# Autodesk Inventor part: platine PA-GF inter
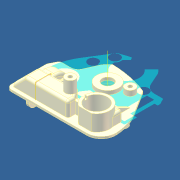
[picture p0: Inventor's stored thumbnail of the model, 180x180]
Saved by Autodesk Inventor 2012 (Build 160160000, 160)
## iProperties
Created: 2011-07
Part Number: platine PA-GF inter
Document SubType Name: Modeling
Designer: Laur
Density: 1.13 g/cm^3
Material: Nylon - 6/6
Mass: 2.66326 g
Surface Area: 28.7081 cm^2
Volume: 2.35687 cm^3
Author: Laur
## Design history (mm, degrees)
sketch "Esquisse1"
  geometry: L1 (-32.1, 11.5)-(26.596, 11.5); L2 (26.596, 11.5)-(26.596, -43.876); L3 (26.596, -43.876)-(-32.1, -43.876); L4 (-32.1, -43.876)-(-32.1, 11.5); L5 (-26.823, -26.616)-(23.17, -27.471); L6 (-20.7, -5)-(-20.7, -19.1); L7 (12.39, -21.5)-(-18.3, -21.5); L8 (9.43, 5.794)-(15.506, -3.93); L9 (-20.482, -4.092)-(-19.208, -1.592); L10 (-13.9, -0.5)-(-17.426, -0.5); L11 (-9.341, 6.094)-(-11.616, 0.983); L12 (-6.696, 9.093)-(-8.758, 6.958); L13 (-20.1, -19.1)-(-20.1, -5); L14 (-19.947, -4.364)-(-18.674, -1.864); L15 (-17.426, -1.1)-(-13.9, -1.1); L16 (-11.068, 0.739)-(-8.793, 5.85); L17 (-8.326, 6.541)-(-6.447, 8.488); L18 (9.025, 5.31)-(14.997, -4.248); L19 (12.39, -20.9)-(-18.3, -20.9); C1 r 1.77 at (0, 0); C2 r 0.8 at (6.9, 2.25); C3 r 4.3 at (10.3, -14.8); C4 r 1.053 at (-10.659, -17.286); C5 r 2 at (0, -15.2); C6 r 2 at (6.9, 2.25); C7 r 0.8 at (0, -15.2); C8 r 1.77 at (-1.149, -7.006); A1 r 2.4 centre (-18.3, -19.1) between (-20.7, -19.1) and (-18.3, -21.5); A2 r 6.5 centre (12.39, -15) between (12.39, -21.5) and (18.882, -14.673); A3 r 22.4 centre (-3.49, -15.8) between (18.882, -14.673) and (15.506, -3.93); A4 r 2 centre (-18.7, -5) between (-20.482, -4.092) and (-20.7, -5); A5 r 2 centre (-17.426, -2.5) between (-17.426, -0.5) and (-19.208, -1.592); A6 r 2.5 centre (-13.9, 2) between (-13.9, -0.5) and (-11.616, 0.983); A7 r 3 centre (-6.6, 4.874) between (-8.758, 6.958) and (-9.341, 6.094); A8 r 45 centre (-7.5, -35.9) between (9.43, 5.794) and (-6.696, 9.093); A9 r 1.4 centre (-18.7, -5) between (-19.947, -4.364) and (-20.1, -5); A10 r 1.4 centre (-17.426, -2.5) between (-17.426, -1.1) and (-18.674, -1.864); A11 r 3.1 centre (-13.9, 2) between (-13.9, -1.1) and (-11.068, 0.739); A12 r 2.4 centre (-6.6, 4.874) between (-8.326, 6.541) and (-8.793, 5.85); A13 r 44.4 centre (-7.5, -35.9) between (9.025, 5.31) and (-6.447, 8.488); A14 r 21.8 centre (-3.49, -15.8) between (18.282, -14.703) and (14.997, -4.248); A15 r 5.9 centre (12.39, -15) between (12.39, -20.9) and (18.282, -14.703); A16 r 1.8 centre (-18.3, -19.1) between (-20.1, -19.1) and (-18.3, -20.9); 1 further point; 1 other entity
  constraints: 32 point on circle, 30 end point, 24 centre point, 13 tangent, 3 coincident, 2 parallel, 2 perpendicular, 1 horizontal, 1 vertical, 16 other
  dimensions: "d44" = 50 distance of L5.start L5.end; "d141" = 3.54 diameter of C1; "d142" = 4 diameter of C6; "d143" = 1.6 diameter of C2; "d144" = 4 diameter of C5 (= d142); "d145" = 1.6 diameter of C7 (= d143); "d150" = 2.4 radius of A1; "d176" = 2.25 vertical distance of C6.centre point (0, 0); "d181" = 21.5 distance from line of L7 point (0, 0); "d184" = 20.7 distance from line of point (0, 0) L6; "d205" = 13 diameter of A2; "d206" = 58 deg angle of L7 L8; "d210" = 6.9 horizontal distance of C2.centre point (0, 0); "d211" = 0 horizontal distance of C7.centre point (0, 0); "d212" = 15.2 distance of C7.centre point (0, 0); "d243" = 15.8 vertical distance of A3.centre point (0, 0); "d244" = 3.49 horizontal distance of point (0, 0) A3.centre; "d245" = 10.3 horizontal distance of C3.centre point (0, 0); "d246" = 14.8 vertical distance of point (0, 0) C3.centre; "d254" = 22.4 radius of A3; "d261" = 8.6 diameter of C3; "d268" = 27 deg angle of L6 L9; "d279" = 16.5 distance from line of L6.start L7; "d280" = 4 diameter of A4; "d281" = 21 distance between parallel lines of L10 L7; "d284" = 4 diameter of A5; "d302" = 114 deg angle of L10 L11; "d308" = 5 diameter of A6; "d309" = 6.8 distance from line of A6.centre L6; "d317" = 6 diameter of A7; "d320" = 6.6 horizontal distance of A7.centre point (0, 0); "d322" = 160 deg angle of L12 L11; "d326" = 90 diameter of A8; "d327" = 7.5 horizontal distance of A8.centre C1.centre; "d328" = 35.9 vertical distance of A8.centre C1.centre; "d335" = 0.6 distance between parallel lines of L6 L13; "d349" = 38.38239 distance from line of A14.start L13 (derived); "d388" = 3.54 diameter of C8; "d499" = 11.5 distance from line of L1 point (0, 0); "d500" = 32.1 distance from line of point (0, 0) L4; "d502" = 7.1 distance of C8.centre point (0, 0)
extrude "contour ext - ép 0,8" new body sketch "Esquisse1" distance "d336" = 0.8; taper "d337" = 0 deg
sketch "Esquisse2"
  geometry: L1 (20.1, -19.1)-(20.1, -5) reference; L2 (19.947, -4.364)-(18.674, -1.864) reference; L3 (17.426, -1.1)-(13.9, -1.1) reference; L4 (11.068, 0.739)-(8.793, 5.85) reference; L5 (8.326, 6.541)-(6.447, 8.488) reference; L6 (-9.025, 5.31)-(-14.997, -4.248) reference; L7 (-12.39, -20.9)-(18.3, -20.9) reference; L8 (-13.81, -4.99)-(-8.082, 4.177); L9 (5.87, 7.069)-(7.319, 5.568); L10 (7.514, 5.281)-(9.789, 0.17); L11 (13.9, -2.5)-(17.426, -2.5); L12 (17.426, -2.5)-(18.7, -5); L13 (18.7, -5)-(18.7, -19.1); L14 (18.3, -19.5)-(-12.39, -19.5); C1 r 4.3 at (-10.3, -14.8) reference; C2 r 2 at (-6.9, 2.25) reference; C3 r 2 at (0, -15.2) reference; C4 r 1.77 at (0, 0) reference; C5 r 1.053 at (10.659, -17.286) reference; A1 r 1.4 centre (18.7, -5) between (20.1, -5) and (19.947, -4.364) reference; A2 r 1.4 centre (17.426, -2.5) between (18.674, -1.864) and (17.426, -1.1) reference; A3 r 3.1 centre (13.9, 2) between (11.068, 0.739) and (13.9, -1.1) reference; A4 r 2.4 centre (6.6, 4.874) between (8.793, 5.85) and (8.326, 6.541) reference; A5 r 44.4 centre (7.5, -35.9) between (6.447, 8.488) and (-9.025, 5.31) reference; A6 r 21.8 centre (3.49, -15.8) between (-14.997, -4.248) and (-18.282, -14.703) reference; A7 r 5.9 centre (-12.39, -15) between (-18.282, -14.703) and (-12.39, -20.9) reference; A8 r 1.8 centre (18.3, -19.1) between (18.3, -20.9) and (20.1, -19.1) reference; A9 r 43 centre (7.5, -35.9) between (5.87, 7.069) and (-8.082, 4.177); A10 r 1 centre (6.6, 4.874) between (7.514, 5.281) and (7.319, 5.568); A11 r 4.5 centre (13.9, 2) between (9.789, 0.17) and (13.9, -2.5); A12 r 0 centre (17.426, -2.5) between (17.426, -2.5) and (17.426, -2.5); A13 r 0 centre (18.7, -5) between (18.7, -5) and (18.7, -5); A14 r 0.4 centre (18.3, -19.1) between (18.3, -19.5) and (18.7, -19.1); A15 r 4.5 centre (-12.39, -15) between (-16.884, -14.774) and (-12.39, -19.5); A16 r 20.4 centre (3.49, -15.8) between (-13.81, -4.99) and (-16.884, -14.774); 2 further points
  constraints: 14 end point, 12 point on circle, 8 centre point, 4 coincident with centre, 14 other
  dimensions: "d518" = 1.4 distance between parallel lines of L1 L13
extrude "centrage int - ép 0,8" join sketch "Esquisse2" distance "d339" = 0.8; taper "d340" = 0 deg
sketch "Esquisse3"
  geometry: C1 r 2 at (6.9, 2.25) reference; C2 r 0.8 at (6.9, 2.25)
  constraints: 1 centre point, 1 coincident
  dimensions: "d341" = 1.6 diameter of C2
extrude "bossage1 fix capot" join sketch "Esquisse3" stored distance "d342" = 5.8; taper "d343" = 0 deg
sketch "Esquisse4"
  geometry: C1 r 2 at (0, 0) reference; C2 r 0.8 at (0, 0)
  constraints: 1 centre point, 1 coincident
  dimensions: "d344" = 1.6 diameter of C2
extrude "alésage1 pour vis fix capot" cut sketch "Esquisse4" distance "d345" = 5; taper "d346" = 0 deg
sketch "Esquisse5"
  geometry: L1 (13.81, -4.99)-(8.082, 4.177) reference; L2 (-5.87, 7.069)-(-7.319, 5.568) reference; L3 (-7.514, 5.281)-(-9.789, 0.17) reference; L4 (-13.9, -2.5)-(-17.426, -2.5) reference; L5 (-17.426, -2.5)-(-18.7, -5) reference; L6 (-18.7, -5)-(-18.7, -19.1) reference; L7 (-18.3, -19.5)-(12.39, -19.5) reference; L8 (3.4, -19.5)-(-18.7, -19.5); L9 (-18.7, -19.5)-(-18.7, -13.2); L10 (-18.7, -13.2)-(1.041, -13.2); L11 (3.4, -16.569)-(3.4, -19.5); L12 (1.041, -13.2)-(3.4, -16.569); C1 r 2 at (0, -15.2) reference; A1 r 43 centre (-7.5, -35.9) between (8.082, 4.177) and (-5.87, 7.069) reference; A2 r 1 centre (-6.6, 4.874) between (-7.319, 5.568) and (-7.514, 5.281) reference; A3 r 4.5 centre (-13.9, 2) between (-13.9, -2.5) and (-9.789, 0.17) reference; A4 r 0.4 centre (-18.3, -19.1) between (-18.7, -19.1) and (-18.3, -19.5) reference; A5 r 4.5 centre (12.39, -15) between (12.39, -19.5) and (16.884, -14.774) reference; A6 r 20.4 centre (-3.49, -15.8) between (16.884, -14.774) and (13.81, -4.99) reference
  constraints: 10 end point, 2 parallel, 2 point on line, 2 tangent, 1 horizontal, 1 perpendicular
  dimensions: "d521" = 55 deg angle of L10 L12; "d522" = 22.1 distance between parallel lines of L11 L6
extrude "bossage loge carte" join sketch "Esquisse5" distance "d523" = 6; taper "d524" = 0 deg
sketch "Esquisse6"
  geometry: C1 r 2 at (0, -15.2); A1 r 2 centre (0, -15.2) between (0, -13.2) and (1.638, -14.053) reference
  constraints: 1 centre point, 1 coincident, 1 concentric
extrude "bossage2 fix capot" join sketch "Esquisse6" distance "d525" = 4.8; taper "d526" = 0 deg
sketch "Esquisse7"
  geometry: C1 r 2 at (0, -15.2) reference; C2 r 0.8 at (0, -15.2)
  constraints: 1 centre point, 1 coincident
  dimensions: "d530" = 1.6 diameter of C2
extrude "alésage2 pour vis fix capot" cut sketch "Esquisse7" distance "d528" = 5; taper "d529" = 0 deg
sketch "Esquisse8"
  geometry: L1 (1.041, -13.2)-(1.638, -14.053); L2 (1.638, -14.053)-(3.4, -16.569); L3 (-17.426, -1.1)-(-13.9, -1.1); L4 (15.45, -13.351)-(15.45, -9.25); L5 (15.45, -9.25)-(9.549, -9.25); L6 (9.549, -9.25)-(1.041, -13.2); L7 (7.744, -19.5)-(12.856, -19.5); L8 (3.4, -19.5)-(-18.3, -19.5); L9 (3.4, -16.569)-(5.251, -16.569); L10 (3.4, -19.5)-(-18.7, -19.5) reference; C1 r 4.3 at (10.3, -14.8); C2 r 4.3 at (10.3, -14.8) reference; A1 r 5.35 centre (10.3, -14.8) between (12.856, -19.5) and (7.744, -19.5)
  constraints: 18 end point, 4 point on circle, 2 centre point, 2 coincident, 2 collinear, 2 parallel, 2 perpendicular, 1 tangent
  dimensions: "d531" = 10.7 diameter of A1; "d533" = 5.55 distance from line of L5 C1.centre; "d534" = 5.15 distance from line of L4 C1.centre
extrude "bossage connect ph1" join sketch "Esquisse8" distance "d535" = 2.3; taper "d536" = 0 deg
sketch "Esquisse9"
  geometry: L1 (15.45, -9.25)-(15.45, -13.351) reference; L2 (9.549, -9.25)-(15.45, -9.25) reference; L3 (1.041, -13.2)-(9.549, -9.25) reference; L4 (5.251, -16.569)-(3.4, -16.569) reference; L5 (12.856, -19.5)-(7.744, -19.5) reference; C1 r 4.3 at (10.3, -14.8) reference; A1 r 5.35 centre (10.3, -14.8) between (12.856, -19.5) and (15.45, -13.351) reference; A2 r 5.35 centre (10.3, -14.8) between (5.251, -16.569) and (7.744, -19.5) reference; A3 r 5.35 centre (10.3, -14.8) between (8.047, -9.947) and (5.251, -16.569)
  constraints: 3 point on circle, 2 point on line, 1 centre point, 1 coincident, 1 end point
extrude "bossage connect ph2" join sketch "Esquisse9" distance "d537" = 1.8; taper "d538" = 0 deg
sketch "Esquisse10"
  geometry: L1 (12.856, -19.5)-(7.744, -19.5) reference; L2 (15.45, -9.25)-(15.45, -13.351) reference; L3 (9.549, -9.25)-(15.45, -9.25) reference; L4 (8.047, -9.947)-(9.549, -9.25) reference; C1 r 4.3 at (10.3, -14.8) reference; A1 r 5.35 centre (10.3, -14.8) between (12.856, -19.5) and (15.45, -13.351) reference; A2 r 5.35 centre (10.3, -14.8) between (8.047, -9.947) and (7.744, -19.5) reference; A3 r 5.35 centre (10.3, -14.8) between (15.45, -13.351) and (8.047, -9.947)
  constraints: 2 end point, 2 point on circle, 1 centre point, 1 coincident, 1 concentric, 1 point on line
extrude "bossage connect ph3" join sketch "Esquisse10" distance "d539" = 2.4; taper "d540" = 0 deg
sketch "Esquisse12"
  geometry: L1 (3.4, -16.569)-(1.041, -13.2) reference; L2 (5.251, -16.569)-(3.4, -16.569) reference; L3 (2.7, -15.569)-(5.006, -15.569); A1 r 5.35 centre (10.3, -14.8) between (8.047, -9.947) and (5.251, -16.569) reference
  constraints: 2 end point, 1 parallel, 1 point on circle, 1 point on line
  dimensions: "d541" = 1 distance between parallel lines of L2 L3
extrude "nervure connect à  loge carte" join sketch "Esquisse12" distance "d542" = 2.4; taper "d543" = 0 deg
node "Plan de construction1"
sketch "Esquisse14"
  geometry: L1 (1.6, 2.851)-(1.6, -5.749) reference; L2 (0, 0)-(-4.1, 0) reference; L3 (0, 4.101)-(0, 0) reference; L4 (0, 4.101)-(-4.1, 4.101) reference; L5 (-4.1, 4.101)-(-4.1, 0) reference; L6 (-3, 4.101)-(0, 10.101); L7 (0, -1.352)-(0, 9.103) reference; L8 (0, 18.661)-(0, 9.103) reference
  constraints: 2 end point, 2 point on line
  dimensions: "d548" = 6 distance from line of L6.end L4; "d549" = 3 distance from line of L6.start L7
feature "Nervure connect à platine" sketch "Esquisse14" dims "d550" = 1, "d551" = 1, "d552" = 0
node "Plan de construction bossage lat"
sketch "Esquisse16"
  geometry: L1 (0, 0.4)-(0, 14.5); L2 (2.5, 5.9)-(2.5, 10.4); L3 (0, 15.136)-(0, 14.5); L4 (0, 15.136)-(0, 17.636); L5 (0, 6)-(0, 15.273); A1 r 6 centre (-3.5, 10.4) between (2.5, 10.4) and (0, 15.273); 2 further points; 1 other entity
  constraints: 10 end point, 2 point on circle, 1 centre point, 1 parallel, 1 point on line, 1 tangent, 4 other
  dimensions: "d554" = 12 diameter of A1; "d555" = 4.5 dimension on A1.centre; "d556" = 2.5 distance between parallel lines of L2 L1
extrude "bossage latéral loge carte" join sketch "Esquisse16" stored distance "d557" = 5.3; taper "d558" = 0 deg
sketch "Esquisse20"
  geometry: L1 (2.5, 6.3)-(2.5, 10.4) reference; L2 (1.3, 3.323)-(1.3, 10.2); L3 (-1.6, 14.5)-(-1.6, 0.4) reference; L4 (1.3, 3.323)-(-1.6, 3.323); L5 (-1.6, 14.5)-(-1.6, 14.812); A1 r 6 centre (-3.5, 10.4) between (2.5, 10.4) and (0, 15.273) reference; A2 r 4.804 centre (-3.5, 10.4) between (1.3, 10.2) and (-1.6, 14.812)
  constraints: 6 end point, 2 perpendicular, 2 point on circle, 1 centre point, 1 point on line
  dimensions: "d564" = 1.2 distance between parallel lines of L2 L1
extrude "évidemment bossage lat" cut sketch "Esquisse20" stored distance "d565" = 2.9; taper "d566" = 0 deg
sketch "Esquisse22"
  geometry: 2 further points
  constraints: 1 other
extrude "Extrusion17" join sketch "Esquisse22" stored distance "d574" = 6; taper "d575" = 0 deg
sketch "Esquisse21"
  geometry: L1 (18.7, -13.2)-(0, -13.2) reference; L2 (-3.4, -16.569)-(-3.4, -19.5) reference; L3 (-1.638, -14.053)-(-3.4, -16.569) reference; L4 (-1.041, -13.2)-(-1.638, -14.053) reference; L5 (0, -13.2)-(-1.041, -13.2) reference; L6 (18.3, -19.5)-(-12.39, -19.5) reference; L7 (-2.2, -18.3)-(17.5, -18.3); L8 (17.5, -18.3)-(17.5, -14.4); L9 (17.5, -14.4)-(-0.416, -14.4); L10 (-0.416, -14.4)-(-2.2, -16.947); L11 (-2.2, -16.947)-(-2.2, -18.3); L12 (18.7, -19.5)-(18.7, -13.2) reference; L13 (-3.4, -19.5)-(18.7, -19.5) reference; C1 r 2 at (0, -15.2) reference; A1 r 2 centre (0, -15.2) between (-1.638, -14.053) and (0, -13.2) reference; A2 r 2 centre (0, -15.2) between (0, -13.2) and (-1.638, -14.053) reference
  constraints: 10 end point, 4 parallel, 1 perpendicular
  dimensions: "d569" = 1.2 distance between parallel lines of L7 L6; "d570" = 1.2 distance between parallel lines of L2 L11 (derived); "d571" = 1.2 distance between parallel lines of L3 L10 (derived); "d572" = 1.2 distance between parallel lines of L1 L9 (derived)
extrude "forme1 logement pcb" cut sketch "Esquisse21" distance "d567" = 6.4; taper "d568" = 0 deg
sketch "Esquisse23"
  geometry: L1 (0, 6)-(0, 0) reference; L2 (0, 0)-(18.7, 0) reference; L3 (4.5, 0)-(0, 4.5)
  constraints: 2 end point, 2 point on line
  dimensions: "d576" = 4.5 distance from line of L1 L3.start; "d577" = 4.5 distance from line of L3.end L2
extrude "forme2 logement pcb" cut sketch "Esquisse23" stored distance "d578" = 6; taper "d579" = 0 deg
sketch "Esquisse24"
  geometry: L1 (-2.35, 6.4)-(-4.45, 4.3) reference; L2 (-4.45, 0)-(-4.45, 4.3) reference; L3 (-2.35, 6.4)-(13.466, 6.4) reference; L4 (-0.653, 6.4)-(-4.45, 2.603)
  constraints: 2 end point, 2 point on line, 1 parallel
  dimensions: "d580" = 1.2 distance between parallel lines of L1 L4
extrude "forme3 logement pcb" join sketch "Esquisse24" stored distance "d581" = 6; taper "d582" = 0 deg
fillet "arrondis platine" dims "d583" = 1
node "Axe de construction1"
sketch "Esquisse25"
  geometry: L1 (6.029, -15.3)-(4.95, -15.3); L2 (4.95, -15.3)-(4.95, -14.3); L3 (4.95, -14.3)-(6.029, -14.3); L4 (6.029, -14.3)-(6.029, -15.3); A1 r 4.3 centre (10.3, -14.8) between (6.029, -14.3) and (6.029, -15.3) reference; A2 r 5.35 centre (10.3, -14.8) between (12.856, -19.5) and (7.744, -19.5) reference
  constraints: 8 end point, 2 parallel, 2 point on circle, 1 horizontal, 1 perpendicular, 1 tangent
  dimensions: "d586" = 1 distance between parallel lines of L1 L3
extrude "évidemment pour ergot connecteur" cut sketch "Esquisse25" distance "d587" = 1; taper "d588" = 0 deg
sketch "Esquisse26"
  geometry: L1 (-0.416, -14.4)-(17.5, -14.4) reference; L2 (18.7, -5)-(18.7, -19.1) reference; L3 (18.7, -14.4)-(17.4, -14.4); L4 (17.4, -14.4)-(17.4, -6); L5 (17.4, -6)-(18.7, -6); L6 (18.7, -6)-(18.7, -14.4); 1 further point
  constraints: 8 end point, 2 parallel, 1 collinear, 1 horizontal, 1 perpendicular, 1 point on line
  dimensions: "d589" = 8.4 distance between parallel lines of L3 L5; "d590" = 1.3 distance between parallel lines of L6 L4
extrude "forme logement butée axiale" join sketch "Esquisse26" distance "d591" = 8.5; taper "d592" = 0 deg
fillet "arrondi forme logement butée axiale" dims "d593" = 2
sketch "Esquisse27"
  geometry: L1 (-0.8, 4.7)-(-7.3, 4.7) reference; L2 (-0.8, 4.7)-(-0.8, 0) reference; L3 (-7.9, 6.35)-(-2.8, 6.35); L4 (-2.8, 6.35)-(-2.8, 11.45); L5 (-2.8, 11.45)-(-7.9, 11.45); L6 (-7.9, 11.45)-(-7.9, 6.35); 1 further point
  constraints: 8 end point, 2 parallel, 1 horizontal, 1 perpendicular
  dimensions: "d594" = 5.1 distance between parallel lines of L5 L3; "d595" = 5.1 distance between parallel lines of L4 L6; "d596" = 1.65 distance between parallel lines of L1 L3; "d597" = 2 distance between parallel lines of L2 L4
extrude "logement butée axiale" cut sketch "Esquisse27" distance "d598" = 1; taper "d599" = 0 deg
sketch "Esquisse28"
  geometry: L1 (18.7, -12.4)-(17.4, -12.4) reference; L2 (17.4, -12.4)-(17.4, -8) reference; L3 (17.4, -11.85)-(17.9, -11.85); L4 (17.9, -11.85)-(17.9, -8.55); L5 (17.9, -8.55)-(17.4, -8.55); L6 (17.4, -8.55)-(17.4, -11.85)
  constraints: 8 end point, 2 parallel, 1 horizontal, 1 perpendicular, 1 point on line
  dimensions: "d600" = 3.3 distance between parallel lines of L5 L3; "d601" = 0.55 distance between parallel lines of L1 L3; "d602" = 0.5 distance between parallel lines of L2 L4
extrude "evidemment1 pour extrémité arbre vis" cut sketch "Esquisse28" distance "d603" = 4.5; taper "d604" = 0 deg
sketch "Esquisse29"
  geometry: L1 (-4.8, 10.55)-(-4.8, 7.25) reference; L2 (-4.8, 7.25)-(-7.9, 7.25) reference; A1 r 1.65 centre (-4.8, 8.9) between (-4.8, 7.25) and (-4.8, 10.55)
  constraints: 2 end point, 2 point on circle, 1 centre point, 1 midpoint
extrude "evidemment2 pour extrémité arbre vis" cut sketch "Esquisse29" stored distance "d605" = 4.5; taper "d606" = 0 deg
sketch "Esquisse30"
  geometry: L1 (15.95, -14.4)-(17.4, -14.4) reference; L2 (10.69, -3.7)-(-9.81, -3.7); C1 r 1.7 at (10.69, -3.7) reference; C2 r 1.7 at (10.69, -3.7) reference; C3 r 1 at (-9.81, -3.7) reference; C4 r 1 at (10.69, -3.7) reference; C5 r 0.665 at (10.69, -3.7); C6 r 0.665 at (-9.81, -3.7); C7 r 1.77 at (0, 0) reference; A1 r 2 centre (10.69, -3.7) between (11.19, -5.636) and (8.798, -3.051) reference; A2 r 1.7 centre (-9.81, -3.7) between (-8.443, -2.689) and (-8.112, -3.616) reference; A3 r 1.7 centre (-9.81, -3.7) between (-8.443, -2.689) and (-8.112, -3.616) reference; A4 r 1.7 centre (-9.81, -3.7) between (-8.443, -2.689) and (-8.112, -3.616) reference; A5 r 1.7 centre (-9.81, -3.7) between (-8.443, -2.689) and (-8.112, -3.616) reference; A6 r 2 centre (-9.81, -3.7) between (-8.47, -2.216) and (-11.461, -2.571) reference; 1 further point
  constraints: 5 coincident, 2 centre point, 2 end point, 1 parallel, 9 other
  dimensions: "d616" = 1.33 diameter of C5; "d617" = 1.33 diameter of C6 (derived); "d672" = 3.7 distance from line of L2 C7.centre (derived)
  node "Référence1"
  node "Référence2"
  node "Référence3"
  node "Référence4"
  node "Référence5"
  node "Référence6"
  node "Référence7"
  node "Référence8"
  node "Référence9"
  node "Référence10"
node "Plan de construction4"
extrude "piliers cage" join sketch "Esquisse30" stored distance "d618" = 4.5; taper "d619" = 0 deg
sketch "Esquisse31"
  geometry: C1 r 2 at (0, 0) reference; C2 r 2 at (-20.5, 0) reference; C3 r 1.7 at (0, 0) reference; A1 r 1.7 centre (-20.5, 0) between (-19.133, 1.011) and (-18.802, 0.084) reference; 1 further point
  constraints: 1 coincident, 3 other
extrude "centrages cage" join sketch "Esquisse31" distance "d620" = 1; taper "d621" = 0 deg
sketch "Esquisse32"
  geometry: C1 r 1.77 at (0, 0) reference; C2 r 2 at (-6.9, 2.25) reference; C3 r 3.75 at (0, 0); A1 r 5.25 centre (0, 0) between (-5.236, 0.384) and (-4.456, 2.776); A2 r 2.5 centre (-6.9, 2.25) between (-4.456, 2.776) and (-5.236, 0.384)
  constraints: 4 point on circle, 3 centre point, 3 coincident
  dimensions: "d624" = 10.5 diameter of A1; "d625" = 7.5 diameter of C3; "d626" = 5 diameter of A2
extrude "bossage pour palier" join sketch "Esquisse32" distance "d627" = 2.5; taper "d628" = 0 deg
sketch "Esquisse33"
  geometry: C1 r 1.77 at (0, 0) reference; C2 r 4.5 at (0, 0); C3 r 2.25 at (0, 0)
  constraints: 2 centre point, 2 coincident
  dimensions: "d629" = 9 diameter of C2; "d630" = 4.5 diameter of C3
extrude "bossage pour joint" join sketch "Esquisse33" distance "d631" = 1.5; taper "d632" = 0 deg
sketch "Esquisse34"
  geometry: C1 r 2.25 at (0, 0) reference
extrude "passage arbre de sortie" cut sketch "Esquisse34" stored distance "d633" = 5; taper "d634" = 0 deg
sketch "Esquisse35"
  geometry: C1 r 2.25 at (0, 0) reference; C2 r 3.75 at (0, 0) reference; C3 r 3.4 at (0, 0)
  constraints: 1 centre point, 1 coincident
  dimensions: "d635" = 6.8 diameter of C3
extrude "logement joint torique" cut sketch "Esquisse35" distance "d636" = 2; taper "d637" = 0 deg
node "Plan de construction nervure 2"
sketch "Esquisse36"
  geometry: L1 (4.8, 1.2)-(4.8, 5.1) reference; L2 (4.8, 5.1)-(-1.6, 5.1) reference; L3 (-1.6, 5.1)-(-1.6, 14.062) reference; L4 (-1.6, 14.062)-(-7.05, 14.062) reference; L5 (-7.05, 14.062)-(-7.05, 14.418) reference; L6 (-7.05, 14.418)-(-6.05, 14.418) reference; L7 (-6.05, 14.418)-(-6.05, 17.182) reference; L8 (-6.05, 17.182)-(-7.05, 17.182) reference; L9 (-7.05, 17.182)-(-7.05, 17.538) reference; L10 (-7.05, 17.538)-(-1.6, 17.538) reference; L11 (-1.6, 17.538)-(-1.6, 19.87) reference; L12 (-1.6, 19.87)-(-0.8, 19.87) reference; L13 (-0.8, 19.87)-(-0.8, 23.312) reference; L14 (-0.8, 23.312)-(0, 23.312) reference; L15 (0, 23.312)-(0, 6.3) reference; L16 (0, 6.3)-(5, 6.3) reference; L17 (6, 5.3)-(6, 1) reference; L18 (5, 0)-(0, 0) reference; L19 (0, 0)-(0, -1.4) reference; L20 (0, -1.4)-(-0.8, -1.4) reference; L21 (-0.8, -1.4)-(-0.8, 0) reference; L22 (-0.8, 0)-(-1.6, 0) reference; L23 (-1.6, 0)-(-1.6, 1.2) reference; L24 (-1.6, 1.2)-(4.8, 1.2) reference; L25 (4, 6.3)-(0, 13.3); L26 (0, 13.3)-(0, 6.3); L27 (0, 6.3)-(4, 6.3); L28 (4, 6.3)-(0, 13.3); L29 (0, 13.3)-(0, 6.3); L30 (4, 6.3)-(0, 6.3); A1 r 1 centre (5, 5.3) between (6, 5.3) and (5, 6.3) reference; A2 r 1 centre (5, 1) between (5, 0) and (6, 1) reference
  constraints: 12 end point, 5 collinear, 2 point on line
  dimensions: "d638" = 7 distance from line of L25.end L16; "d639" = 4 distance from line of L15 L25.start
feature "Nervure2 logement pcb" sketch "Esquisse36" dims "d640" = 1, "d641" = 1.1, "d642" = 0
node "Plan de construction nervure 3"
sketch "Esquisse37"
  geometry: L1 (-1.3, -1.931)-(-1.3, 2.369) reference; L2 (-0.3, 3.369)-(4.7, 3.369) reference; L3 (4.7, 18.424)-(4.7, 24.938) reference; L4 (4.7, 24.938)-(5.5, 24.938) reference; L5 (5.5, 24.938)-(5.5, 23.534) reference; L6 (6.3, 13.29)-(6.3, 2.169) reference; L7 (6.3, 2.169)-(-0.1, 2.169) reference; L8 (-0.1, 2.169)-(-0.1, -1.731) reference; L9 (-0.1, -1.731)-(6.3, -1.731) reference; L10 (6.3, -1.731)-(6.3, -2.931) reference; L11 (6.3, -2.931)-(5.5, -2.931) reference; L12 (5.5, -2.931)-(5.5, -4.331) reference; L13 (5.5, -4.331)-(4.7, -4.331) reference; L14 (4.7, -4.331)-(4.7, -2.931) reference; L15 (4.7, -2.931)-(-0.3, -2.931) reference; L16 (1.2, 3.369)-(4.7, 7.369); L17 (5.5, 23.534)-(6.3, 23.534) reference; L18 (6.3, 23.534)-(6.3, 19.848) reference; L19 (6.3, 19.848)-(8.8, 19.848) reference; L20 (8.8, 19.848)-(8.8, 13.29) reference; L21 (8.8, 13.29)-(6.3, 13.29) reference; L22 (4.7, 3.369)-(4.7, 14.714) reference; L23 (4.7, 14.714)-(3.2, 14.714) reference; L24 (3.2, 14.714)-(3.2, 18.424) reference; L25 (3.2, 18.424)-(4.7, 18.424) reference; A1 r 1 centre (-0.3, 2.369) between (-0.3, 3.369) and (-1.3, 2.369) reference; A2 r 1 centre (-0.3, -1.931) between (-1.3, -1.931) and (-0.3, -2.931) reference
  constraints: 2 end point, 2 point on line
  dimensions: "d644" = 3.5 distance from line of L3 L16.start; "d645" = 4 distance from line of L2 L16.end
feature "Nervure3 logement pcb" sketch "Esquisse37" dims "d646" = 1, "d647" = 1.1, "d648" = 0
sketch "Esquisse38"
  geometry: L1 (3.354, 4.039)-(6.07, 6.862); L2 (-2.711, 4.496)-(-3.43, 5.688); L3 (4.524, 6.4)-(-2, 5.4); L4 (-2, 5.4)-(-2.094, 6.016); L5 (-0.893, 5.57)-(-0.998, 6.252); L6 (0.204, 5.738)-(0.094, 6.457); L7 (2.122, 6.032)-(2.012, 6.748); L8 (4.524, 6.4)-(4.433, 6.991); L9 (3.219, 6.2)-(3.115, 6.876); L10 (5.87, 7.069)-(7.319, 5.568) reference; L11 (0, 0)-(-3.43, 5.688); L12 (0, 0)-(-3.43, 5.688); A1 r 5.25 centre (0, 0) between (-5.236, 0.384) and (-4.456, 2.776) reference; 2 further points
  constraints: 22 end point, 5 parallel, 5 point on line, 2 collinear, 2 point on circle, 1 perpendicular, 8 other
  dimensions: "d651" = 2.71108 horizontal distance of L11.start L2.start; "d652" = 3.35397 horizontal distance of L11.start L1.start; "d653" = 6.6 distance of L3.start L3.end; "d654" = 2 horizontal distance of L3.end L11.start; "d655" = 5.4 vertical distance of L3.end L11.start; "d656" = 6.4 vertical distance of L11.start L3.start; "d657" = 1.11991 distance between parallel lines of L4 L5; "d658" = 1.11 distance between parallel lines of L7 L9; "d659" = 1.32 distance between parallel lines of L8 L9; "d660" = 1.94 distance between parallel lines of L6 L7; "d661" = 1.11009 distance between parallel lines of L5 L6 (derived); "d664" = 9.5 horizontal distance of L1.end L2.end
extrude "languette de butée roue de sortie" join sketch "Esquisse38" distance "d662" = 6; taper "d663" = 0 deg
sketch "Esquisse39"
  geometry: A1 r 2 centre (0, 0) between (1.998, -0.094) and (1.438, 1.39) reference; A2 r 5.25 centre (9.81, 3.7) between (7.099, 8.196) and (5.354, 6.476) reference; A3 r 8.685 centre (9.81, 3.7) between (1.438, 1.39) and (1.998, -0.094)
  constraints: 4 point on circle, 1 centre point, 1 coincident
  dimensions: "d666" = 0.2 dimension on A1 A3
extrude "correction pilier cage pour roue de sortie" cut sketch "Esquisse39" stored distance "d667" = 10; taper "d668" = 0 deg
node "Solide1"
node "Corps solides"
node "Corps surfaciques"
node "Image1"
node "Boucle projetée1"
node "Boucle projetée2"
node "Boucle projetée3"
node "Boucle projetée4"
node "Boucle projetée13"
node "Boucle projetée14"
node "Référence11"
node "Référence12"
node "Projeter les arêtes coupées1"
node "Projeter les arêtes coupées2"
other parameters: "d229" = 45, "d547" = -3.65, "d614" = -4.2, "d615" = -9, "d643" = -7.5
